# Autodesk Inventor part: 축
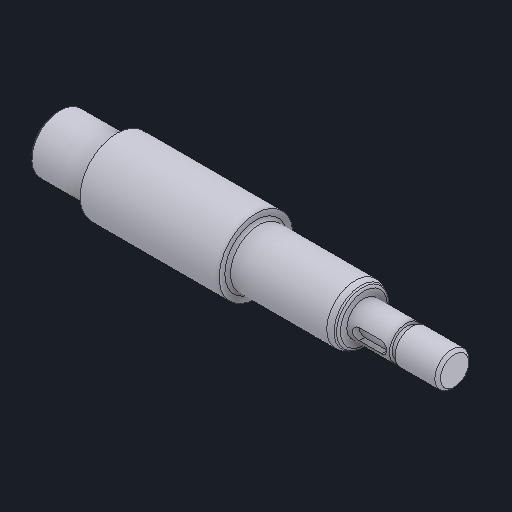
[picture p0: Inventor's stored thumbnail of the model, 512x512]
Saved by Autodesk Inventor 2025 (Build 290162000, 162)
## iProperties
Created: 2025-08
Part Number: 축
Material: 강철, 연강
Document SubType Name: Modeling
Designer: infra08
Density: 7.86 g/cm^3
Appearance: 기본값
Author: jhkim
Sending System: Autodesk Inventor 2026
Preprocessor: ST-DEVELOPER v20.1
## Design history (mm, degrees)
feature "솔리드2"
node "솔리드1"
